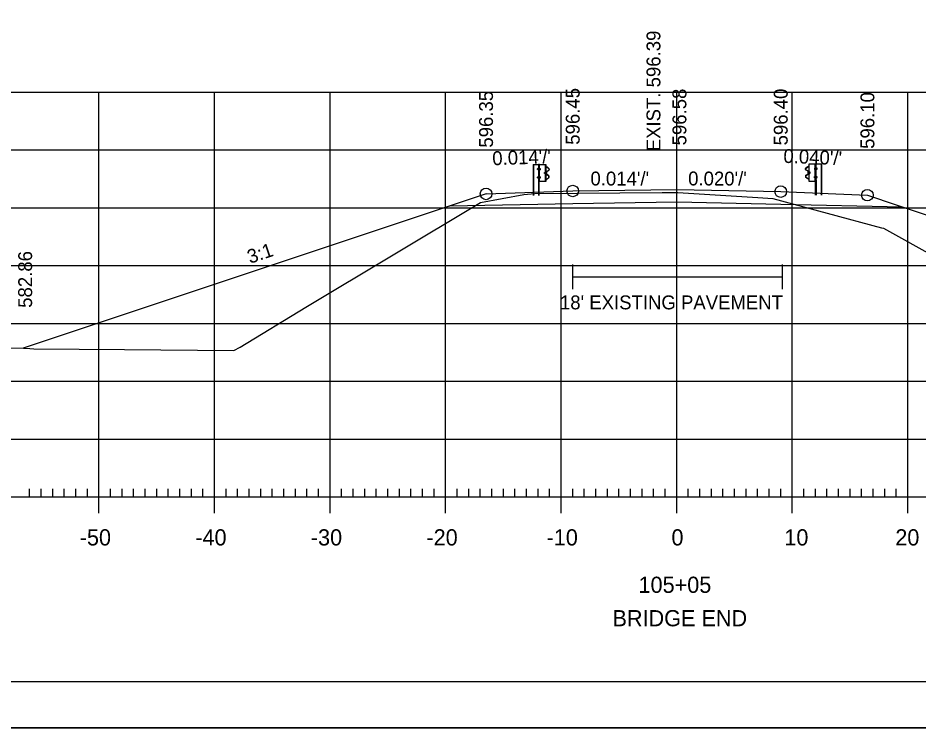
# Model space of a CAD drawing. Extents: x 961436 to 1372525, y 380079 to 2027791.
# Drawn here: x 1371137.9 to 1371215.8, y 380535.8 to 380597.1 of the extents above; entities that cross this region are included whole.
import ezdxf

# ---------------------------------------------------------------- set-up
doc = ezdxf.new("R2010")
doc.units = 0
for name, color, linetype in [('R_Alt Surface', 7, 'Continuous'), ('R_Axis', 7, 'Continuous'), ('R_Axis Annot', 7, 'Continuous'), ('R_Border', 7, 'Continuous'), ('R_Drive', 7, 'Continuous'), ('R_Exist Surface', 7, 'Continuous'), ('R_Fin Surface', 7, 'Continuous'), ('R_Fin Surface Annot', 7, 'Continuous'), ('R_Grid', 7, 'Continuous'), ('R_No Plot', 7, 'Continuous'), ('R_Proposed Road', 7, 'Continuous'), ('R_Xsect Elev', 7, 'Continuous')]:
    doc.layers.add(name, color=color, linetype=linetype)

msp = doc.modelspace()

# ---------------------------------------------------------------- linework, layer by layer
at = {"layer": 'R_Alt Surface'}
for points in [[(1371175.245, 380580.893), (1371185.877, 380581.106), (1371194.877, 380581.243), (1371203.877, 380581.048), (1371214.41, 380580.821)], [(1371178.377, 380581.937), (1371175.877, 380581.104)], [(1371211.377, 380581.832), (1371213.877, 380580.998)], [(1371175.877, 380581.104), (1371138.336, 380568.59)], [(1371213.877, 380580.998), (1371254.671, 380567.4)]]:
    msp.add_lwpolyline(points, dxfattribs=at)
at = {"layer": 'R_Axis'}
for p, q in [((1371144.877, 380554.335), (1371144.877, 380557.135)), ((1371154.877, 380554.335), (1371154.877, 380557.135)), ((1371164.877, 380554.335), (1371164.877, 380557.135)), ((1371174.877, 380554.335), (1371174.877, 380557.135)), ((1371184.877, 380554.335), (1371184.877, 380557.135)), ((1371194.877, 380554.335), (1371194.877, 380557.135)), ((1371204.877, 380554.335), (1371204.877, 380557.135)), ((1371214.877, 380554.335), (1371214.877, 380557.135)), ((1371138.877, 380555.735), (1371138.877, 380556.435)), ((1371139.877, 380555.735), (1371139.877, 380556.435)), ((1371140.877, 380555.735), (1371140.877, 380556.435)), ((1371141.877, 380555.735), (1371141.877, 380556.435)), ((1371142.877, 380555.735), (1371142.877, 380556.435)), ((1371143.877, 380555.735), (1371143.877, 380556.435)), ((1371145.877, 380555.735), (1371145.877, 380556.435)), ((1371146.877, 380555.735), (1371146.877, 380556.435)), ((1371147.877, 380555.735), (1371147.877, 380556.435)), ((1371148.877, 380555.735), (1371148.877, 380556.435)), ((1371149.877, 380555.735), (1371149.877, 380556.435)), ((1371150.877, 380555.735), (1371150.877, 380556.435)), ((1371151.877, 380555.735), (1371151.877, 380556.435)), ((1371152.877, 380555.735), (1371152.877, 380556.435)), ((1371153.877, 380555.735), (1371153.877, 380556.435)), ((1371155.877, 380555.735), (1371155.877, 380556.435)), ((1371156.877, 380555.735), (1371156.877, 380556.435)), ((1371157.877, 380555.735), (1371157.877, 380556.435)), ((1371158.877, 380555.735), (1371158.877, 380556.435)), ((1371159.877, 380555.735), (1371159.877, 380556.435)), ((1371160.877, 380555.735), (1371160.877, 380556.435)), ((1371161.877, 380555.735), (1371161.877, 380556.435)), ((1371162.877, 380555.735), (1371162.877, 380556.435)), ((1371163.877, 380555.735), (1371163.877, 380556.435)), ((1371165.877, 380555.735), (1371165.877, 380556.435)), ((1371166.877, 380555.735), (1371166.877, 380556.435)), ((1371167.877, 380555.735), (1371167.877, 380556.435)), ((1371168.877, 380555.735), (1371168.877, 380556.435)), ((1371169.877, 380555.735), (1371169.877, 380556.435)), ((1371170.877, 380555.735), (1371170.877, 380556.435)), ((1371171.877, 380555.735), (1371171.877, 380556.435)), ((1371172.877, 380555.735), (1371172.877, 380556.435)), ((1371173.877, 380555.735), (1371173.877, 380556.435)), ((1371175.877, 380555.735), (1371175.877, 380556.435)), ((1371176.877, 380555.735), (1371176.877, 380556.435)), ((1371177.877, 380555.735), (1371177.877, 380556.435)), ((1371178.877, 380555.735), (1371178.877, 380556.435)), ((1371179.877, 380555.735), (1371179.877, 380556.435)), ((1371180.877, 380555.735), (1371180.877, 380556.435)), ((1371181.877, 380555.735), (1371181.877, 380556.435)), ((1371182.877, 380555.735), (1371182.877, 380556.435)), ((1371183.877, 380555.735), (1371183.877, 380556.435)), ((1371185.877, 380555.735), (1371185.877, 380556.435)), ((1371186.877, 380555.735), (1371186.877, 380556.435)), ((1371187.877, 380555.735), (1371187.877, 380556.435)), ((1371188.877, 380555.735), (1371188.877, 380556.435)), ((1371189.877, 380555.735), (1371189.877, 380556.435)), ((1371190.877, 380555.735), (1371190.877, 380556.435)), ((1371191.877, 380555.735), (1371191.877, 380556.435)), ((1371192.877, 380555.735), (1371192.877, 380556.435)), ((1371193.877, 380555.735), (1371193.877, 380556.435)), ((1371195.877, 380555.735), (1371195.877, 380556.435)), ((1371196.877, 380555.735), (1371196.877, 380556.435)), ((1371197.877, 380555.735), (1371197.877, 380556.435)), ((1371198.877, 380555.735), (1371198.877, 380556.435)), ((1371199.877, 380555.735), (1371199.877, 380556.435)), ((1371200.877, 380555.735), (1371200.877, 380556.435)), ((1371201.877, 380555.735), (1371201.877, 380556.435)), ((1371202.877, 380555.735), (1371202.877, 380556.435)), ((1371203.877, 380555.735), (1371203.877, 380556.435)), ((1371205.877, 380555.735), (1371205.877, 380556.435)), ((1371206.877, 380555.735), (1371206.877, 380556.435)), ((1371207.877, 380555.735), (1371207.877, 380556.435)), ((1371208.877, 380555.735), (1371208.877, 380556.435)), ((1371209.877, 380555.735), (1371209.877, 380556.435)), ((1371210.877, 380555.735), (1371210.877, 380556.435)), ((1371211.877, 380555.735), (1371211.877, 380556.435)), ((1371212.877, 380555.735), (1371212.877, 380556.435)), ((1371213.877, 380555.735), (1371213.877, 380556.435)), ((1371054.877, 380555.735), (1371334.877, 380555.735))]:
    msp.add_line(p, q, dxfattribs=at)
at = {"layer": 'R_Border'}
msp.add_line((1371353.057, 380539.735), (1371036.877, 380539.735), dxfattribs=at)
at = {"layer": 'R_Drive'}
for p, q in [((1371185.863, 380575.84), (1371185.863, 380573.704)), ((1371203.991, 380575.84), (1371203.991, 380573.704)), ((1371185.863, 380574.772), (1371203.991, 380574.772))]:
    msp.add_line(p, q, dxfattribs=at)
at = {"layer": 'R_Exist Surface'}
msp.add_lwpolyline([(1371125.566, 380568.882), (1371138.341, 380568.59), (1371138.905, 380568.562), (1371139.247, 380568.552), (1371147.096, 380568.493), (1371156.56, 380568.393), (1371157.092, 380568.672), (1371162.796, 380572.143), (1371177.892, 380581.184), (1371181.66, 380581.895), (1371182.608, 380581.986), (1371193.628, 380582.062), (1371194.966, 380582.05), (1371201.908, 380581.625), (1371203.192, 380581.54), (1371212.61, 380579.003), (1371212.761, 380578.961), (1371213.798, 380578.403), (1371229.025, 380569.917), (1371231.796, 380568.191), (1371234.475, 380568.125), (1371241.292, 380568.058), (1371255.586, 380567.355), (1371266.594, 380567.357)], dxfattribs=at)
at = {"layer": 'R_Fin Surface'}
msp.add_lwpolyline([(1371178.377, 380581.937), (1371185.877, 380582.189), (1371194.877, 380582.326), (1371203.877, 380582.132), (1371211.377, 380581.832)], dxfattribs=at)
at = {"layer": 'R_Grid'}
for p, q in [((1371054.877, 380590.735), (1371334.877, 380590.735)), ((1371144.877, 380555.735), (1371144.877, 380590.735)), ((1371154.877, 380555.735), (1371154.877, 380590.735)), ((1371164.877, 380555.735), (1371164.877, 380590.735)), ((1371174.877, 380555.735), (1371174.877, 380590.735)), ((1371184.877, 380555.735), (1371184.877, 380590.735)), ((1371194.877, 380555.735), (1371194.877, 380590.735)), ((1371204.877, 380555.735), (1371204.877, 380590.735)), ((1371214.877, 380555.735), (1371214.877, 380590.735)), ((1371054.877, 380585.735), (1371334.877, 380585.735)), ((1371054.877, 380580.735), (1371334.877, 380580.735)), ((1371054.877, 380575.735), (1371334.877, 380575.735)), ((1371054.877, 380570.735), (1371334.877, 380570.735)), ((1371054.877, 380565.735), (1371334.877, 380565.735)), ((1371054.877, 380560.735), (1371334.877, 380560.735)), ((1371054.877, 380555.735), (1371334.877, 380555.735))]:
    msp.add_line(p, q, dxfattribs=at)
at = {"layer": 'R_No Plot'}
msp.add_line((1371024.476, 380535.756), (1371357.81, 380535.756), dxfattribs=at)
for points in [[(1371024.47, 380749.09), (1371357.81, 380749.09), (1371357.81, 380535.752), (1371024.47, 380535.752)], [(1371270.797, 380745.195), (1371290.417, 380745.195), (1371290.417, 380735.315), (1371306.529, 380735.315), (1371329.729, 380735.315), (1371329.849, 380707.158), (1371353.057, 380707.158), (1371353.057, 380539.735), (1371036.877, 380539.735), (1371036.877, 380745.195)]]:
    msp.add_lwpolyline(points, close=True, dxfattribs=at)
for centre in [(1371178.377, 380581.937), (1371185.877, 380582.189), (1371203.877, 380582.132), (1371211.377, 380581.832)]:
    msp.add_circle(centre, 0.5, dxfattribs=at)
at = {"layer": 'R_Proposed Road'}
for p, q in [((1371182.443, 380584.469), (1371182.443, 380581.799)), ((1371182.475, 380584.469), (1371182.475, 380581.799)), ((1371183, 380584.471), (1371182.927, 380584.468)), ((1371182.964, 380581.799), (1371182.964, 380584.471)), ((1371183, 380584.471), (1371182.994, 380584.471)), ((1371183.53, 380583.019), (1371183.53, 380584.463)), ((1371206.171, 380584.274), (1371206.29, 380584.338)), ((1371206.324, 380583.051), (1371206.324, 380584.495)), ((1371206.853, 380584.504), (1371206.86, 380584.504)), ((1371206.853, 380584.504), (1371206.927, 380584.501)), ((1371206.889, 380581.831), (1371206.889, 380584.504)), ((1371207.379, 380584.502), (1371207.379, 380581.832)), ((1371207.411, 380584.502), (1371207.411, 380581.832)), ((1371182.868, 380584.034), (1371182.868, 380584.133)), ((1371182.926, 380584.017), (1371182.873, 380584.017)), ((1371182.926, 380584.118), (1371182.874, 380584.118)), ((1371182.926, 380584.05), (1371182.874, 380584.05)), ((1371182.926, 380584.149), (1371182.875, 380584.149)), ((1371182.926, 380584.05), (1371182.88, 380584.05)), ((1371182.926, 380584.017), (1371182.926, 380584.149)), ((1371183.059, 380584.077), (1371182.999, 380584.077)), ((1371183.007, 380584.011), (1371183.06, 380584.011)), ((1371183.008, 380584.144), (1371183.06, 380584.144)), ((1371183.06, 380584.144), (1371183.06, 380584.011)), ((1371183.458, 380583.692), (1371183.458, 380583.793)), ((1371183.516, 380583.676), (1371183.463, 380583.676)), ((1371183.516, 380583.776), (1371183.464, 380583.776)), ((1371183.516, 380583.708), (1371183.464, 380583.708)), ((1371183.516, 380583.809), (1371183.465, 380583.809)), ((1371183.516, 380583.708), (1371183.471, 380583.708)), ((1371183.516, 380583.676), (1371183.516, 380583.809)), ((1371183.683, 380584.242), (1371183.564, 380584.305)), ((1371183.669, 380584.225), (1371183.57, 380584.278)), ((1371183.572, 380583.677), (1371183.574, 380583.816)), ((1371183.597, 380583.676), (1371183.599, 380583.816)), ((1371183.781, 380583.494), (1371183.616, 380583.597)), ((1371183.621, 380583.889), (1371183.804, 380584.001)), ((1371183.793, 380583.516), (1371183.63, 380583.619)), ((1371183.635, 380583.867), (1371183.818, 380583.978)), ((1371183.807, 380584.114), (1371183.669, 380584.225)), ((1371183.821, 380584.131), (1371183.683, 380584.242)), ((1371206.033, 380584.164), (1371206.171, 380584.274)), ((1371206.218, 380583.9), (1371206.036, 380584.011)), ((1371206.046, 380584.147), (1371206.184, 380584.257)), ((1371206.232, 380583.922), (1371206.05, 380584.033)), ((1371206.06, 380583.548), (1371206.224, 380583.651)), ((1371206.073, 380583.527), (1371206.238, 380583.63)), ((1371206.184, 380584.257), (1371206.283, 380584.311)), ((1371206.257, 380583.709), (1371206.255, 380583.849)), ((1371206.282, 380583.71), (1371206.28, 380583.849)), ((1371206.337, 380583.709), (1371206.337, 380583.841)), ((1371206.337, 380583.841), (1371206.388, 380583.841)), ((1371206.337, 380583.808), (1371206.389, 380583.808)), ((1371206.337, 380583.74), (1371206.383, 380583.74)), ((1371206.337, 380583.74), (1371206.389, 380583.74)), ((1371206.337, 380583.709), (1371206.39, 380583.709)), ((1371206.396, 380583.725), (1371206.396, 380583.825)), ((1371206.846, 380584.177), (1371206.794, 380584.177)), ((1371206.794, 380584.177), (1371206.794, 380584.044)), ((1371206.847, 380584.044), (1371206.794, 380584.044)), ((1371206.795, 380584.11), (1371206.854, 380584.11)), ((1371206.928, 380584.049), (1371206.928, 380584.182)), ((1371206.928, 380584.182), (1371206.979, 380584.182)), ((1371206.928, 380584.15), (1371206.98, 380584.15)), ((1371206.928, 380584.082), (1371206.973, 380584.082)), ((1371206.928, 380584.082), (1371206.98, 380584.082)), ((1371206.928, 380584.049), (1371206.981, 380584.049)), ((1371206.986, 380584.066), (1371206.986, 380584.166)), ((1371182.857, 380583.301), (1371182.857, 380583.402)), ((1371182.915, 380583.385), (1371182.862, 380583.385)), ((1371182.915, 380583.317), (1371182.862, 380583.317)), ((1371182.915, 380583.285), (1371182.862, 380583.285)), ((1371182.915, 380583.418), (1371182.863, 380583.418)), ((1371182.915, 380583.317), (1371182.87, 380583.317)), ((1371182.915, 380583.285), (1371182.915, 380583.418)), ((1371182.999, 380583.019), (1371182.963, 380583.019)), ((1371183.059, 380583.351), (1371182.999, 380583.351)), ((1371183.06, 380583.285), (1371183.007, 380583.285)), ((1371183.06, 380583.418), (1371183.008, 380583.418)), ((1371183.06, 380583.285), (1371183.06, 380583.418)), ((1371183.56, 380583.191), (1371183.675, 380583.249)), ((1371183.568, 380583.171), (1371183.689, 380583.232)), ((1371183.675, 380583.249), (1371183.808, 380583.365)), ((1371183.689, 380583.232), (1371183.823, 380583.348)), ((1371206.164, 380583.265), (1371206.031, 380583.381)), ((1371206.179, 380583.282), (1371206.045, 380583.398)), ((1371206.285, 380583.203), (1371206.164, 380583.265)), ((1371206.294, 380583.223), (1371206.179, 380583.282)), ((1371206.794, 380583.318), (1371206.794, 380583.451)), ((1371206.794, 380583.451), (1371206.846, 380583.451)), ((1371206.794, 380583.318), (1371206.847, 380583.318)), ((1371206.795, 380583.384), (1371206.854, 380583.384)), ((1371206.854, 380583.051), (1371206.89, 380583.051)), ((1371206.938, 380583.318), (1371206.938, 380583.451)), ((1371206.938, 380583.451), (1371206.99, 380583.451)), ((1371206.938, 380583.418), (1371206.991, 380583.418)), ((1371206.938, 380583.35), (1371206.984, 380583.35)), ((1371206.938, 380583.35), (1371206.991, 380583.35)), ((1371206.938, 380583.318), (1371206.991, 380583.318)), ((1371206.997, 380583.334), (1371206.997, 380583.435))]:
    msp.add_line(p, q, dxfattribs=at)
for points in [[(1371182.443, 380584.469), (1371182.927, 380584.468), (1371182.925, 380581.799)], [(1371207.411, 380584.502), (1371206.927, 380584.501), (1371206.928, 380581.831)]]:
    msp.add_lwpolyline(points, dxfattribs=at)
for points in [[(1371183.558, 380584.47), (1371183.557, 380583.019), (1371182.999, 380583.019), (1371183, 380584.471)], [(1371206.296, 380584.503), (1371206.297, 380583.051), (1371206.854, 380583.051), (1371206.853, 380584.504)], [(1371182.866, 380584.116), (1371182.866, 380584.051), (1371182.839, 380584.051), (1371182.839, 380584.116)], [(1371182.925, 380584.171), (1371182.925, 380583.992), (1371182.936, 380583.992), (1371182.936, 380584.171)], [(1371183.059, 380584.144), (1371183.059, 380584.011), (1371183, 380584.011), (1371183, 380584.144)], [(1371183.456, 380583.776), (1371183.456, 380583.709), (1371183.429, 380583.709), (1371183.429, 380583.776)], [(1371183.515, 380583.83), (1371183.515, 380583.651), (1371183.526, 380583.651), (1371183.526, 380583.83)], [(1371206.338, 380583.863), (1371206.338, 380583.684), (1371206.328, 380583.684), (1371206.328, 380583.863)], [(1371206.398, 380583.808), (1371206.398, 380583.742), (1371206.424, 380583.742), (1371206.424, 380583.808)], [(1371206.795, 380584.177), (1371206.795, 380584.044), (1371206.853, 380584.044), (1371206.853, 380584.177)], [(1371206.929, 380584.203), (1371206.929, 380584.025), (1371206.918, 380584.025), (1371206.918, 380584.203)], [(1371206.988, 380584.149), (1371206.988, 380584.083), (1371207.015, 380584.083), (1371207.015, 380584.149)], [(1371182.854, 380583.385), (1371182.854, 380583.318), (1371182.827, 380583.318), (1371182.827, 380583.385)], [(1371182.913, 380583.439), (1371182.913, 380583.261), (1371182.924, 380583.261), (1371182.924, 380583.439)], [(1371183.059, 380583.418), (1371183.059, 380583.285), (1371183, 380583.285), (1371183, 380583.418)], [(1371206.795, 380583.451), (1371206.795, 380583.318), (1371206.853, 380583.318), (1371206.853, 380583.451)], [(1371206.94, 380583.472), (1371206.94, 380583.294), (1371206.93, 380583.294), (1371206.93, 380583.472)], [(1371207, 380583.418), (1371207, 380583.351), (1371207.026, 380583.351), (1371207.026, 380583.418)]]:
    msp.add_lwpolyline(points, close=True, dxfattribs=at)
for centre, radius, start, end in [((1371182.891, 380584.133), 0.0234, 134.57445, 222.22441), ((1371182.966, 380584.083), 0.0979, 159.74227, 200.25773), ((1371182.895, 380584.033), 0.0265, 140.93341, 216.62337), ((1371183.482, 380583.792), 0.0234, 134.57445, 222.22441), ((1371183.556, 380583.742), 0.0979, 159.74227, 200.25773), ((1371183.485, 380583.691), 0.0265, 140.93341, 216.62337), ((1371183.645, 380583.666), 0.0747, 171.78044, 246.85364), ((1371183.665, 380583.808), 0.0918, 118.10599, 175.04439), ((1371183.591, 380583.737), 0.0481, 282.95537, 86.06973), ((1371183.645, 380583.666), 0.049, 171.78044, 246.85364), ((1371183.665, 380583.808), 0.066, 118.10599, 175.04439), ((1371183.772, 380584.058), 0.0658, 299.24991, 57.97825), ((1371183.772, 380584.058), 0.0909, 299.24991, 57.97825), ((1371206.082, 380584.091), 0.0909, 122.02175, 240.75009), ((1371206.082, 380584.091), 0.0658, 122.02175, 240.75009), ((1371206.262, 380583.77), 0.0481, 93.93027, 257.04463), ((1371206.189, 380583.841), 0.066, 4.95561, 61.89401), ((1371206.208, 380583.699), 0.049, 293.14636, 8.21956), ((1371206.189, 380583.841), 0.0918, 4.95561, 61.89401), ((1371206.208, 380583.699), 0.0747, 293.14636, 8.21956), ((1371206.372, 380583.824), 0.0234, 317.77559, 45.42555), ((1371206.298, 380583.775), 0.0979, 339.74227, 20.25773), ((1371206.369, 380583.724), 0.0265, 323.37663, 39.06659), ((1371206.962, 380584.165), 0.0234, 317.77559, 45.42555), ((1371206.888, 380584.116), 0.0979, 339.74227, 20.25773), ((1371206.959, 380584.065), 0.0265, 323.37663, 39.06659), ((1371182.88, 380583.401), 0.0234, 134.57445, 222.22441), ((1371182.954, 380583.351), 0.0979, 159.74227, 200.25773), ((1371182.883, 380583.301), 0.0265, 140.93341, 216.62337), ((1371183.734, 380583.417), 0.0907, 325.21842, 59.11995), ((1371183.734, 380583.417), 0.116, 325.21843, 59.11995), ((1371206.12, 380583.449), 0.116, 120.88005, 214.78158), ((1371206.12, 380583.449), 0.0907, 120.88005, 214.78158), ((1371206.974, 380583.434), 0.0234, 317.77559, 45.42555), ((1371206.899, 380583.384), 0.0979, 339.74227, 20.25773), ((1371206.97, 380583.334), 0.0265, 323.37663, 39.06659)]:
    msp.add_arc(centre, radius, start, end, dxfattribs=at)

# ---------------------------------------------------------------- texts
at = {"layer": 'R_Axis Annot'}
for s, p in [('-50', (1371143.218, 380551.535)), ('-40', (1371153.218, 380551.535)), ('-30', (1371163.218, 380551.535)), ('-20', (1371173.218, 380551.535)), ('-10', (1371183.615, 380551.535)), ('0', (1371194.42, 380551.535)), ('10', (1371204.188, 380551.535)), ('20', (1371213.791, 380551.535)), ('105+05', (1371191.57, 380547.435)), ('BRIDGE END', (1371189.319, 380544.545))]:
    msp.add_text(s, height=1.4, dxfattribs=at).set_placement(p)
at = {"layer": 'R_Fin Surface Annot'}
for s, rotation, p in [('596.35', 90, (1371178.977, 380585.937)), ('596.45', 90, (1371186.477, 380586.189)), ('596.58', 90, (1371195.71, 380586.132)), ('596.40', 90, (1371204.477, 380586.132)), ('596.10', 90, (1371211.977, 380585.832)), ("0.014'/'", 1.92518, (1371178.937, 380584.414)), ("0.040'/'", 357.70939, (1371204.088, 380584.628)), ("0.014'/'", 359.817, (1371187.41, 380582.67)), ("0.020'/'", 359.817, (1371195.863, 380582.672)), ('3:1', 18.43493, (1371157.953, 380575.886)), ('582.86', 90, (1371139.097, 380572.087))]:
    msp.add_text(s, height=1.2, rotation=rotation, dxfattribs=at).set_placement(p)
msp.add_text("18' EXISTING PAVEMENT", height=1.2, dxfattribs=at).set_placement((1371184.772, 380571.954))
at = {"layer": 'R_Xsect Elev'}
msp.add_text('EXIST. 596.39', height=1.2, rotation=90, dxfattribs=at).set_placement((1371193.464, 380585.621))

doc.saveas('drawing.dxf')
